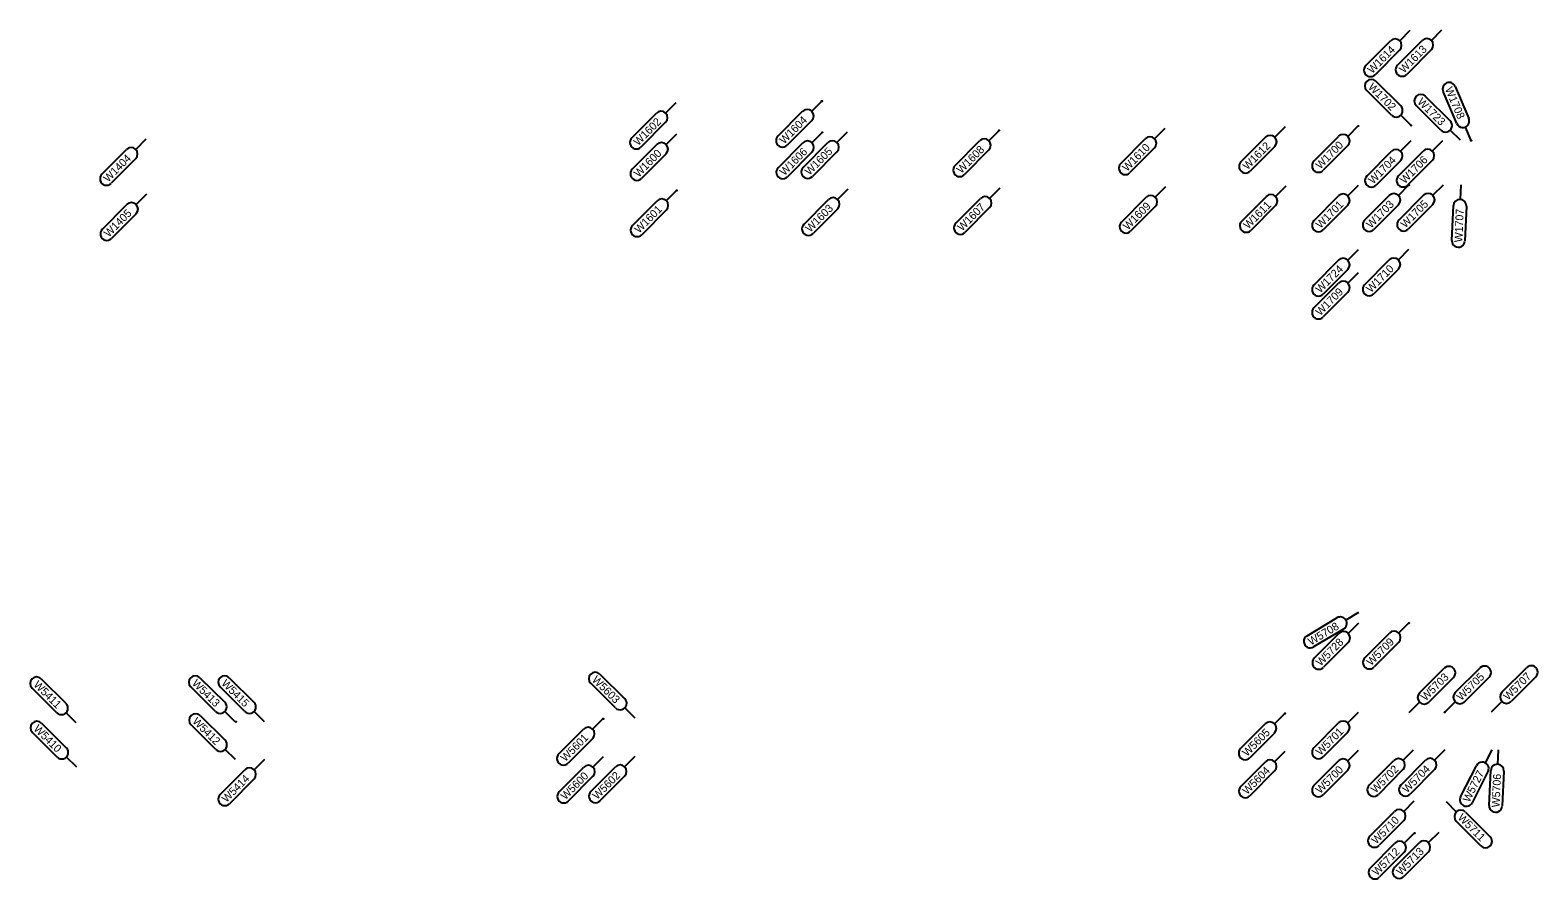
# Model space of a CAD drawing. Extents: x 12479652 to 12487250, y 9842710 to 9846560.
# Drawn here: x 12482533.2 to 12482771.3, y 9842726.5 to 9842860.7 of the extents above; entities that cross this region are included whole.
import ezdxf

# ---------------------------------------------------------------- set-up
doc = ezdxf.new("R2010")
doc.units = 0
doc.layers.add('_CIVIL_CONSTRUCTION', color=7, linetype='Continuous')
doc.layers.add('TextAlignmentLrg', color=7, linetype='Continuous')

msp = doc.modelspace()

# ---------------------------------------------------------------- linework, layer by layer
at = {"layer": '_CIVIL_CONSTRUCTION'}
for p, q in [((12482751.13, 9842860.61), (12482749.51, 9842858.98)), ((12482756.13, 9842860.66), (12482754.51, 9842859.03)), ((12482744.17, 9842855.06), (12482748.06, 9842858.97)), ((12482749.51, 9842857.53), (12482745.62, 9842853.61)), ((12482749.17, 9842855.11), (12482753.06, 9842859.03)), ((12482754.51, 9842857.58), (12482750.62, 9842853.67)), ((12482745.75, 9842852.57), (12482749.66, 9842848.68)), ((12482748.21, 9842847.23), (12482744.3, 9842851.12)), ((12482753.55, 9842850.21), (12482757.46, 9842846.32)), ((12482758.53, 9842845.89), (12482756.37, 9842850.97)), ((12482758.26, 9842851.77), (12482760.42, 9842846.7)), ((12482628.2, 9842843.63), (12482632.09, 9842847.54)), ((12482635.16, 9842849.18), (12482633.54, 9842847.55)), ((12482651.28, 9842843.92), (12482655.17, 9842847.83)), ((12482658.24, 9842849.46), (12482656.62, 9842847.83)), ((12482756.02, 9842844.87), (12482752.1, 9842848.76)), ((12482633.54, 9842846.1), (12482629.65, 9842842.18)), ((12482656.63, 9842846.38), (12482652.74, 9842842.47)), ((12482731.39, 9842845.36), (12482729.77, 9842843.73)), ((12482742.92, 9842845.51), (12482741.3, 9842843.87)), ((12482751.3, 9842845.61), (12482749.66, 9842847.23)), ((12482760.78, 9842843.23), (12482759.88, 9842845.35)), ((12482551.45, 9842843.44), (12482549.83, 9842841.81)), ((12482635.24, 9842844.21), (12482633.62, 9842842.58)), ((12482651.32, 9842838.92), (12482655.21, 9842842.83)), ((12482655.26, 9842838.96), (12482659.15, 9842842.88)), ((12482658.28, 9842844.46), (12482656.66, 9842842.83)), ((12482662.22, 9842844.51), (12482660.6, 9842842.88)), ((12482679.26, 9842839.26), (12482683.15, 9842843.17)), ((12482686.22, 9842844.81), (12482684.6, 9842843.18)), ((12482705.43, 9842839.58), (12482709.32, 9842843.49)), ((12482712.39, 9842845.13), (12482710.77, 9842843.5)), ((12482724.43, 9842839.82), (12482728.32, 9842843.73)), ((12482735.96, 9842839.96), (12482739.85, 9842843.87)), ((12482751.27, 9842843.15), (12482749.65, 9842841.52)), ((12482756.27, 9842843.18), (12482754.65, 9842841.55)), ((12482759.1, 9842843.25), (12482757.47, 9842844.87)), ((12482544.49, 9842837.89), (12482548.38, 9842841.81)), ((12482628.28, 9842838.66), (12482632.17, 9842842.57)), ((12482633.62, 9842841.13), (12482629.73, 9842837.21)), ((12482656.66, 9842841.38), (12482652.77, 9842837.47)), ((12482660.61, 9842841.43), (12482656.72, 9842837.52)), ((12482684.6, 9842841.73), (12482680.71, 9842837.81)), ((12482710.78, 9842842.05), (12482706.89, 9842838.14)), ((12482729.78, 9842842.28), (12482725.89, 9842838.37)), ((12482741.31, 9842842.42), (12482737.42, 9842838.51)), ((12482744.31, 9842837.6), (12482748.2, 9842841.51)), ((12482749.31, 9842837.64), (12482753.2, 9842841.55)), ((12482549.84, 9842840.36), (12482545.95, 9842836.45)), ((12482749.66, 9842840.07), (12482745.77, 9842836.15)), ((12482754.66, 9842840.1), (12482750.77, 9842836.19)), ((12482686.33, 9842835.68), (12482684.71, 9842834.05)), ((12482712.51, 9842835.87), (12482710.89, 9842834.24)), ((12482731.51, 9842836.01), (12482729.89, 9842834.38)), ((12482742.92, 9842836.09), (12482741.3, 9842834.46)), ((12482750.92, 9842836.15), (12482749.3, 9842834.51)), ((12482756.35, 9842836.18), (12482754.73, 9842834.55)), ((12482759.15, 9842836.2), (12482759.05, 9842833.91)), ((12482551.52, 9842834.72), (12482549.9, 9842833.09)), ((12482628.31, 9842829.77), (12482632.2, 9842833.68)), ((12482635.28, 9842835.32), (12482633.65, 9842833.69)), ((12482655.37, 9842829.96), (12482659.26, 9842833.88)), ((12482662.33, 9842835.51), (12482660.71, 9842833.88)), ((12482679.37, 9842830.14), (12482683.26, 9842834.05)), ((12482705.55, 9842830.32), (12482709.44, 9842834.24)), ((12482724.55, 9842830.46), (12482728.44, 9842834.37)), ((12482735.96, 9842830.54), (12482739.85, 9842834.45)), ((12482743.96, 9842830.6), (12482747.85, 9842834.51)), ((12482749.39, 9842830.64), (12482753.28, 9842834.55)), ((12482544.55, 9842829.17), (12482548.44, 9842833.09)), ((12482549.9, 9842831.64), (12482546.01, 9842827.73)), ((12482633.66, 9842832.24), (12482629.77, 9842828.33)), ((12482660.72, 9842832.43), (12482656.83, 9842828.52)), ((12482684.72, 9842832.6), (12482680.83, 9842828.69)), ((12482710.89, 9842832.79), (12482707, 9842828.88)), ((12482729.89, 9842832.92), (12482726, 9842829.01)), ((12482741.31, 9842833.01), (12482737.42, 9842829.09)), ((12482749.31, 9842833.06), (12482745.42, 9842829.15)), ((12482754.73, 9842833.1), (12482750.84, 9842829.19)), ((12482757.75, 9842827.41), (12482757.98, 9842832.92)), ((12482760.03, 9842832.84), (12482759.8, 9842827.33)), ((12482735.96, 9842820.37), (12482739.85, 9842824.28)), ((12482742.92, 9842825.92), (12482741.3, 9842824.29)), ((12482743.96, 9842820.42), (12482747.85, 9842824.33)), ((12482750.92, 9842825.97), (12482749.3, 9842824.34)), ((12482741.31, 9842822.84), (12482737.42, 9842818.92)), ((12482742.92, 9842822.32), (12482741.3, 9842820.68)), ((12482749.31, 9842822.89), (12482745.42, 9842818.97)), ((12482735.96, 9842816.77), (12482739.85, 9842820.68)), ((12482741.31, 9842819.23), (12482737.42, 9842815.32)), ((12482734.86, 9842764.92), (12482739.59, 9842767.75)), ((12482742.97, 9842768.58), (12482741, 9842767.39)), ((12482742.97, 9842766.93), (12482741.35, 9842765.3)), ((12482750.97, 9842766.98), (12482749.34, 9842765.35)), ((12482740.65, 9842765.99), (12482735.91, 9842763.16)), ((12482736.01, 9842761.39), (12482739.9, 9842765.3)), ((12482744, 9842761.44), (12482747.89, 9842765.35)), ((12482741.36, 9842763.85), (12482737.47, 9842759.94)), ((12482749.35, 9842763.9), (12482745.46, 9842759.99)), ((12482752.64, 9842755.89), (12482756.55, 9842759.78)), ((12482758.27, 9842755.94), (12482762.19, 9842759.83)), ((12482765.66, 9842756), (12482769.58, 9842759.89)), ((12482534.91, 9842758.1), (12482538.82, 9842754.21)), ((12482559.98, 9842758.3), (12482563.89, 9842754.41)), ((12482564.61, 9842758.29), (12482568.52, 9842754.4)), ((12482625.63, 9842753.52), (12482621.72, 9842757.41)), ((12482623.17, 9842758.86), (12482627.08, 9842754.97)), ((12482758, 9842758.33), (12482754.09, 9842754.44)), ((12482763.63, 9842758.37), (12482759.72, 9842754.48)), ((12482771.02, 9842758.43), (12482767.11, 9842754.54)), ((12482537.37, 9842752.76), (12482533.46, 9842756.65)), ((12482562.44, 9842752.95), (12482558.53, 9842756.84)), ((12482567.08, 9842752.94), (12482563.16, 9842756.83)), ((12482540.45, 9842751.14), (12482538.82, 9842752.76)), ((12482560.02, 9842752.3), (12482563.94, 9842748.41)), ((12482565.52, 9842751.34), (12482563.89, 9842752.96)), ((12482570.16, 9842751.33), (12482568.53, 9842752.95)), ((12482628.72, 9842751.9), (12482627.08, 9842753.52)), ((12482731.34, 9842752.63), (12482729.72, 9842751)), ((12482742.92, 9842752.78), (12482741.3, 9842751.14)), ((12482751, 9842752.82), (12482752.64, 9842754.44)), ((12482756.64, 9842752.86), (12482758.27, 9842754.49)), ((12482764.03, 9842752.92), (12482765.66, 9842754.55)), ((12482534.96, 9842751.1), (12482538.87, 9842747.21)), ((12482562.49, 9842746.95), (12482558.58, 9842750.84)), ((12482616.67, 9842746.24), (12482620.56, 9842750.16)), ((12482623.63, 9842751.79), (12482622.01, 9842750.16)), ((12482724.38, 9842747.09), (12482728.27, 9842751)), ((12482735.96, 9842747.23), (12482739.85, 9842751.14)), ((12482537.43, 9842745.76), (12482533.51, 9842749.65)), ((12482622.02, 9842748.71), (12482618.13, 9842744.8)), ((12482729.72, 9842749.55), (12482725.83, 9842745.64)), ((12482741.31, 9842749.69), (12482737.42, 9842745.78)), ((12482540.51, 9842744.14), (12482538.88, 9842745.76)), ((12482565.57, 9842745.34), (12482563.94, 9842746.96)), ((12482570.15, 9842745.37), (12482568.53, 9842743.74)), ((12482623.68, 9842745.79), (12482622.06, 9842744.16)), ((12482628.68, 9842745.83), (12482627.06, 9842744.2)), ((12482731.36, 9842746.63), (12482729.74, 9842745)), ((12482735.96, 9842741.23), (12482739.85, 9842745.14)), ((12482742.92, 9842746.77), (12482741.3, 9842745.14)), ((12482744.68, 9842741.29), (12482748.57, 9842745.21)), ((12482749.68, 9842741.33), (12482753.57, 9842745.25)), ((12482751.64, 9842746.84), (12482750.02, 9842745.21)), ((12482756.64, 9842746.88), (12482755.02, 9842745.25)), ((12482764.04, 9842746.89), (12482763, 9842744.84)), ((12482765.06, 9842746.9), (12482764.95, 9842744.6)), ((12482563.19, 9842739.83), (12482567.08, 9842743.74)), ((12482616.72, 9842740.24), (12482620.61, 9842744.16)), ((12482621.72, 9842740.28), (12482625.61, 9842744.2)), ((12482627.06, 9842742.75), (12482623.17, 9842738.84)), ((12482724.4, 9842741.09), (12482728.29, 9842745)), ((12482729.74, 9842743.55), (12482725.85, 9842739.64)), ((12482741.31, 9842743.69), (12482737.42, 9842739.78)), ((12482750.02, 9842743.76), (12482746.14, 9842739.85)), ((12482755.02, 9842743.8), (12482751.14, 9842739.89)), ((12482759.13, 9842739.47), (12482761.62, 9842744.39)), ((12482763.45, 9842743.46), (12482760.96, 9842738.54)), ((12482763.63, 9842738.11), (12482763.88, 9842743.62)), ((12482765.93, 9842743.53), (12482765.68, 9842738.02)), ((12482568.53, 9842742.29), (12482564.64, 9842738.38)), ((12482622.06, 9842742.71), (12482618.17, 9842738.8)), ((12482751.76, 9842738.79), (12482750.14, 9842737.16)), ((12482756.82, 9842738.7), (12482758.44, 9842737.07)), ((12482744.8, 9842733.24), (12482748.69, 9842737.16)), ((12482750.14, 9842735.71), (12482746.25, 9842731.8)), ((12482762.33, 9842731.7), (12482758.44, 9842735.62)), ((12482759.89, 9842737.06), (12482763.78, 9842733.15)), ((12482751.83, 9842733.79), (12482750.21, 9842732.16)), ((12482755.66, 9842733.85), (12482754.04, 9842732.22)), ((12482744.87, 9842728.24), (12482748.76, 9842732.16)), ((12482748.7, 9842728.3), (12482752.59, 9842732.21)), ((12482750.21, 9842730.71), (12482746.32, 9842726.8)), ((12482754.04, 9842730.77), (12482750.15, 9842726.85))]:
    msp.add_line(p, q, dxfattribs=at)
for centre, start, end in [((12482748.78, 9842858.25), 315.1702, 135.1702), ((12482753.78, 9842858.3), 315.1702, 135.1702), ((12482744.89, 9842854.34), 135.1702, 315.1702), ((12482749.89, 9842854.39), 135.1702, 315.1702), ((12482745.02, 9842851.84), 45.1702, 225.1702), ((12482757.31, 9842851.37), 23.0771, 203.0771), ((12482752.83, 9842849.48), 45.1702, 225.1702), ((12482632.81, 9842846.82), 315.1702, 135.1702), ((12482655.9, 9842847.1), 315.1702, 135.1702), ((12482748.94, 9842847.95), 225.1702, 45.1702), ((12482756.74, 9842845.59), 225.1702, 45.1702), ((12482759.47, 9842846.29), 203.0771, 23.0771), ((12482628.92, 9842842.91), 135.1702, 315.1702), ((12482632.9, 9842841.85), 315.1702, 135.1702), ((12482652.01, 9842843.19), 135.1702, 315.1702), ((12482655.94, 9842842.11), 315.1702, 135.1702), ((12482659.88, 9842842.15), 315.1702, 135.1702), ((12482683.88, 9842842.45), 315.1702, 135.1702), ((12482710.05, 9842842.77), 315.1702, 135.1702), ((12482729.05, 9842843), 315.1702, 135.1702), ((12482740.58, 9842843.15), 315.1702, 135.1702), ((12482549.11, 9842841.08), 315.1702, 135.1702), ((12482748.93, 9842840.79), 315.1702, 135.1702), ((12482753.93, 9842840.82), 315.1702, 135.1702), ((12482629.01, 9842837.94), 135.1702, 315.1702), ((12482652.05, 9842838.19), 135.1702, 315.1702), ((12482655.99, 9842838.24), 135.1702, 315.1702), ((12482679.99, 9842838.54), 135.1702, 315.1702), ((12482706.16, 9842838.86), 135.1702, 315.1702), ((12482725.16, 9842839.09), 135.1702, 315.1702), ((12482736.69, 9842839.23), 135.1702, 315.1702), ((12482545.22, 9842837.17), 135.1702, 315.1702), ((12482745.04, 9842836.88), 135.1702, 315.1702), ((12482750.04, 9842836.91), 135.1702, 315.1702), ((12482549.17, 9842832.36), 315.1702, 135.1702), ((12482632.93, 9842832.96), 315.1702, 135.1702), ((12482659.99, 9842833.15), 315.1702, 135.1702), ((12482683.99, 9842833.33), 315.1702, 135.1702), ((12482710.16, 9842833.51), 315.1702, 135.1702), ((12482729.16, 9842833.65), 315.1702, 135.1702), ((12482740.58, 9842833.73), 315.1702, 135.1702), ((12482748.58, 9842833.79), 315.1702, 135.1702), ((12482754.01, 9842833.83), 315.1702, 135.1702), ((12482759.01, 9842832.88), 357.6263, 177.6263), ((12482545.28, 9842828.45), 135.1702, 315.1702), ((12482629.04, 9842829.05), 135.1702, 315.1702), ((12482656.1, 9842829.24), 135.1702, 315.1702), ((12482680.1, 9842829.41), 135.1702, 315.1702), ((12482706.27, 9842829.6), 135.1702, 315.1702), ((12482725.27, 9842829.74), 135.1702, 315.1702), ((12482736.69, 9842829.82), 135.1702, 315.1702), ((12482744.69, 9842829.87), 135.1702, 315.1702), ((12482750.12, 9842829.91), 135.1702, 315.1702), ((12482758.78, 9842827.37), 177.6263, 357.6263), ((12482740.58, 9842823.56), 315.1702, 135.1702), ((12482748.58, 9842823.61), 315.1702, 135.1702), ((12482736.69, 9842819.65), 135.1702, 315.1702), ((12482740.58, 9842819.96), 315.1702, 135.1702), ((12482744.69, 9842819.7), 135.1702, 315.1702), ((12482736.69, 9842816.04), 135.1702, 315.1702), ((12482740.12, 9842766.87), 300.8894, 120.8894), ((12482735.38, 9842764.04), 120.8894, 300.8894), ((12482740.63, 9842764.58), 315.1702, 135.1702), ((12482748.62, 9842764.63), 315.1702, 135.1702), ((12482736.74, 9842760.66), 135.1702, 315.1702), ((12482744.73, 9842760.71), 135.1702, 315.1702), ((12482757.28, 9842759.05), 314.8298, 134.8298), ((12482762.91, 9842759.1), 314.8298, 134.8298), ((12482770.3, 9842759.16), 314.8298, 134.8298), ((12482534.18, 9842757.38), 45.1702, 225.1702), ((12482559.25, 9842757.57), 45.1702, 225.1702), ((12482563.89, 9842757.56), 45.1702, 225.1702), ((12482622.44, 9842758.13), 45.1702, 225.1702), ((12482626.36, 9842754.24), 225.1702, 45.1702), ((12482753.36, 9842755.16), 134.8298, 314.8298), ((12482759, 9842755.21), 134.8298, 314.8298), ((12482766.39, 9842755.27), 134.8298, 314.8298), ((12482538.09, 9842753.49), 225.1702, 45.1702), ((12482559.3, 9842751.57), 45.1702, 225.1702), ((12482563.17, 9842753.68), 225.1702, 45.1702), ((12482567.8, 9842753.67), 225.1702, 45.1702), ((12482534.24, 9842750.38), 45.1702, 225.1702), ((12482621.29, 9842749.43), 315.1702, 135.1702), ((12482728.99, 9842750.28), 315.1702, 135.1702), ((12482740.58, 9842750.42), 315.1702, 135.1702), ((12482563.21, 9842747.68), 225.1702, 45.1702), ((12482538.15, 9842746.49), 225.1702, 45.1702), ((12482617.4, 9842745.52), 135.1702, 315.1702), ((12482725.1, 9842746.36), 135.1702, 315.1702), ((12482729.01, 9842744.28), 315.1702, 135.1702), ((12482736.69, 9842746.5), 135.1702, 315.1702), ((12482740.58, 9842744.42), 315.1702, 135.1702), ((12482749.3, 9842744.48), 315.1702, 135.1702), ((12482754.3, 9842744.52), 315.1702, 135.1702), ((12482567.8, 9842743.02), 315.1702, 135.1702), ((12482621.34, 9842743.43), 315.1702, 135.1702), ((12482626.34, 9842743.47), 315.1702, 135.1702), ((12482762.54, 9842743.92), 333.1225, 153.1225), ((12482764.91, 9842743.58), 357.3933, 177.3933), ((12482725.12, 9842740.36), 135.1702, 315.1702), ((12482736.69, 9842740.5), 135.1702, 315.1702), ((12482745.41, 9842740.57), 135.1702, 315.1702), ((12482750.41, 9842740.61), 135.1702, 315.1702), ((12482563.91, 9842739.1), 135.1702, 315.1702), ((12482617.45, 9842739.52), 135.1702, 315.1702), ((12482622.45, 9842739.56), 135.1702, 315.1702), ((12482760.04, 9842739), 153.1225, 333.1225), ((12482764.66, 9842738.06), 177.3933, 357.3933), ((12482749.41, 9842736.43), 315.1702, 135.1702), ((12482759.17, 9842736.34), 44.8298, 224.8298), ((12482745.52, 9842732.52), 135.1702, 315.1702), ((12482749.49, 9842731.43), 315.1702, 135.1702), ((12482753.31, 9842731.49), 315.1702, 135.1702), ((12482763.06, 9842732.43), 224.8298, 44.8298), ((12482745.6, 9842727.52), 135.1702, 315.1702), ((12482749.42, 9842727.58), 135.1702, 315.1702)]:
    msp.add_arc(centre, 1.03, start, end, dxfattribs=at)
at = {"layer": 'TextAlignmentLrg'}
for centre in [(12482658.21, 9842849.43), (12482742.97, 9842845.51), (12482751.3, 9842845.61), (12482658.28, 9842844.51), (12482686.22, 9842844.81), (12482760.8, 9842843.2), (12482750.97, 9842836.15), (12482635.28, 9842835.32), (12482750.97, 9842766.93), (12482731.39, 9842752.63), (12482756.61, 9842752.83), (12482565.66, 9842751.34), (12482623.68, 9842751.79), (12482751.88, 9842733.74)]:
    msp.add_circle(centre, 0.05, dxfattribs=at)

# ---------------------------------------------------------------- texts
at = {"layer": '_CIVIL_CONSTRUCTION'}
for s, rotation, p in [('W1614', 45.1702, (12482745.16, 9842853.7)), ('W1613', 45.1702, (12482750.17, 9842853.77)), ('W1702', 315.1702, (12482744.42, 9842851.55)), ('W1723', 315.1702, (12482752.21, 9842849.2)), ('W1708', 293.0771, (12482756.63, 9842851.35)), ('W1602', 45.1702, (12482629.22, 9842842.3)), ('W1604', 45.1702, (12482652.27, 9842842.56)), ('W1612', 45.1702, (12482725.45, 9842838.48)), ('W1700', 45.1702, (12482736.96, 9842838.61)), ('W1404', 45.1702, (12482545.48, 9842836.53)), ('W1600', 45.1702, (12482629.28, 9842837.31)), ('W1606', 45.1702, (12482652.31, 9842837.56)), ('W1605', 45.1702, (12482656.27, 9842837.63)), ('W1608', 45.1702, (12482680.26, 9842837.91)), ('W1610', 45.1702, (12482706.43, 9842838.23)), ('W1704', 45.1702, (12482745.3, 9842836.24)), ('W1706', 45.1702, (12482750.31, 9842836.28)), ('W1607', 45.1702, (12482680.38, 9842828.8)), ('W1609', 45.1702, (12482706.55, 9842828.97)), ('W1611', 45.1702, (12482725.58, 9842829.14)), ('W1701', 45.1702, (12482737, 9842829.22)), ('W1703', 45.1702, (12482744.97, 9842829.25)), ('W1705', 45.1702, (12482750.4, 9842829.3)), ('W1405', 45.1702, (12482545.57, 9842827.84)), ('W1601', 45.1702, (12482629.35, 9842828.46)), ('W1603', 45.1702, (12482656.38, 9842828.62)), ('W1707', 87.6263, (12482759.4, 9842827.1)), ('W1724', 45.1702, (12482736.95, 9842819.01)), ('W1710', 45.1702, (12482744.96, 9842819.07)), ('W1709', 45.1702, (12482736.96, 9842815.42)), ('W5708', 30.8894, (12482735.49, 9842763.36)), ('W5728', 45.1702, (12482737.01, 9842760.04)), ('W5709', 45.1702, (12482745, 9842760.09)), ('W5411', 315.1702, (12482533.59, 9842757.07)), ('W5413', 315.1702, (12482558.63, 9842757.29)), ('W5415', 315.1702, (12482563.27, 9842757.28)), ('W5603', 315.1702, (12482621.82, 9842757.85)), ('W5703', 44.8298, (12482753.6, 9842754.54)), ('W5705', 44.8298, (12482759.24, 9842754.58)), ('W5707', 44.8298, (12482766.63, 9842754.64)), ('W5410', 315.1702, (12482533.61, 9842750.1)), ('W5412', 315.1702, (12482558.69, 9842751.28)), ('W5605', 45.1702, (12482725.39, 9842745.75)), ('W5701', 45.1702, (12482737, 9842745.91)), ('W5601', 45.1702, (12482617.71, 9842744.93)), ('W5414', 45.1702, (12482564.18, 9842738.47)), ('W5600', 45.1702, (12482617.72, 9842738.89)), ('W5602', 45.1702, (12482622.74, 9842738.95)), ('W5604', 45.1702, (12482725.39, 9842739.73)), ('W5700', 45.1702, (12482736.96, 9842739.87)), ('W5702', 45.1702, (12482745.7, 9842739.96)), ('W5704', 45.1702, (12482750.67, 9842739.98)), ('W5727', 63.1225, (12482760.5, 9842738.5)), ('W5706', 87.3933, (12482765.28, 9842737.78)), ('W5710', 45.1702, (12482745.8, 9842731.89)), ('W5711', 314.8298, (12482758.57, 9842736.07)), ('W5712', 45.1702, (12482745.89, 9842726.91)), ('W5713', 45.1702, (12482749.7, 9842726.96))]:
    msp.add_text(s, height=1.25, rotation=rotation, dxfattribs=at).set_placement(p)

doc.saveas('drawing.dxf')
